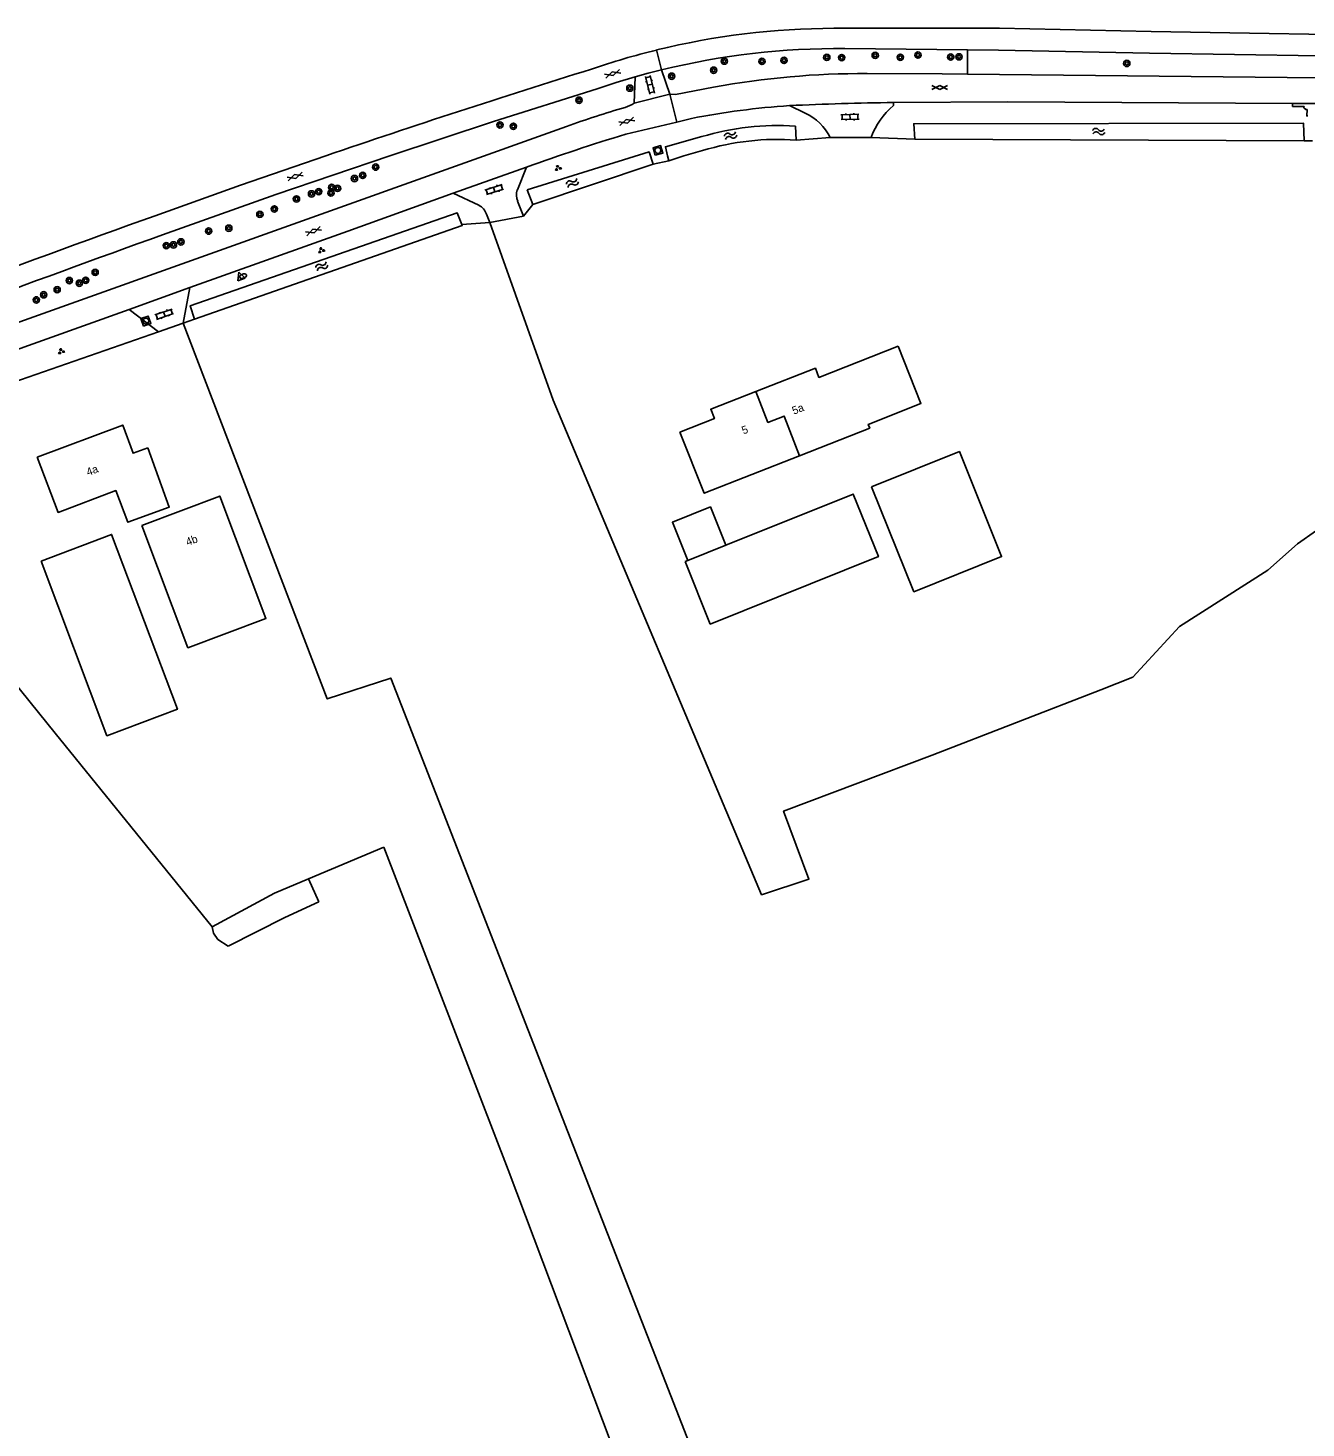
# Model space of a CAD drawing. Extents: x 134297 to 137000, y 403500 to 406000.
# Drawn here: x 136615.3 to 136777.7, y 405338.4 to 405516.2 of the extents above; entities that cross this region are included whole.
import ezdxf

# ---------------------------------------------------------------- set-up
doc = ezdxf.new("R2010")
doc.units = 0
for name, color, linetype in [('gg-afsc-draadraster', 7, 'Continuous'), ('gg-afsc-erfafscheiding', 7, 'Continuous'), ('gg-anno-huisnummerreeks BGT', 7, 'Continuous'), ('gg-bbg-bijgebouw', 7, 'Continuous'), ('gg-bbg-gedigitaliseerde bebouwing', 7, 'Continuous'), ('gg-bbg-gedigitaliseerde bijgebouw', 7, 'Continuous'), ('gg-bbg-hoofdgebouw', 7, 'Continuous'), ('gg-bbg-luifel en loopbrug', 7, 'Continuous'), ('gg-bbg-tussenscheiding', 7, 'Continuous'), ('gg-knt-bronhoudergrens', 7, 'Continuous'), ('gg-knt-verharding', 7, 'Continuous'), ('gg-kntw-bovenkant insteek waterloop', 7, 'Continuous'), ('gt-grn-groengrens', 7, 'Continuous'), ('gt-grn-weggrens', 7, 'Continuous'), ('gt-symb-boom', 7, 'Continuous'), ('gt-symb-brandkraan', 7, 'Continuous'), ('gt-symb-gesloten verharding', 7, 'Continuous'), ('gt-symb-groenvak', 7, 'Continuous'), ('gt-symb-klinker verharding', 7, 'Continuous'), ('gt-symb-rioolschacht', 7, 'Continuous'), ('gt-symb-waterafsluiter', 7, 'Continuous'), ('gt-symb-watersymbool', 7, 'Continuous')]:
    doc.layers.add(name, color=color, linetype=linetype)

# ---------------------------------------------------------------- blocks, each defined once
blk = doc.blocks.new('gt0-BOOM')
at = {"layer": 'gt-symb-boom'}
for radius in [0.4, 0.2]:
    blk.add_circle((0, 0), radius, dxfattribs=at)
blk = doc.blocks.new('gt0-GESVH1')
at = {"layer": 'gt-symb-gesloten verharding'}
for p, q in [((-0.99, -0.26), (0.01, 0.24)), ((0.01, -0.26), (-0.99, 0.24)), ((0.01, 0.24), (1.01, -0.26)), ((1.01, 0.24), (0.01, -0.26))]:
    blk.add_line(p, q, dxfattribs=at)
blk = doc.blocks.new('gt0-WA')
at = {"layer": 'gt-symb-watersymbool'}
for centre, start, end in [((-0.32, 0.02), 28.0725, 151.9275), ((0.43, 0.42), 208.0725, 331.9275), ((-0.32, -0.43), 28.0725, 151.9275), ((0.43, -0.03), 208.0725, 331.9275)]:
    blk.add_arc(centre, 0.425, start, end, dxfattribs=at)
blk = doc.blocks.new('gt0-KL1')
at = {"layer": 'gt-symb-klinker verharding'}
for p, q in [((-1.15, 0.3), (1.15, 0.3)), ((-1, -0.3), (-1, 0.3)), ((-0.5, 0.3), (-0.5, 0.45)), ((0, -0.3), (0, 0.3)), ((0.5, 0.3), (0.5, 0.45)), ((1, -0.3), (1, 0.3)), ((-1.15, -0.3), (1.15, -0.3)), ((-0.5, -0.45), (-0.5, -0.3)), ((0.5, -0.45), (0.5, -0.3))]:
    blk.add_line(p, q, dxfattribs=at)
blk = doc.blocks.new('gt0-RS')
at = {"layer": 'gt-symb-rioolschacht'}
blk.add_lwpolyline([(-0.5, -0.5), (0.5, -0.5), (0.5, 0.5), (-0.5, 0.5)], close=True, dxfattribs=at)
blk.add_circle((0, 0), 0.375, dxfattribs=at)
blk = doc.blocks.new('gt0-GRVAK')
at = {"layer": 'gt-symb-groenvak'}
for p, q in [((-0.11, 0.19), (-0.23, 0.24)), ((-0.18, 0.15), (0.09, 0.15)), ((-0.09, 0.21), (-0.16, 0.32)), ((-0.05, 0.21), (-0.05, 0.39)), ((0, 0.21), (0.06, 0.32)), ((0.01, 0.19), (0.13, 0.24)), ((0.26, -0.05), (0.2, 0.06)), ((0.3, -0.05), (0.3, 0.13)), ((0.35, -0.05), (0.41, 0.06)), ((-0.24, -0.23), (-0.36, -0.18)), ((-0.32, -0.26), (-0.05, -0.26)), ((-0.23, -0.21), (-0.29, -0.09)), ((-0.18, -0.2), (-0.18, -0.02)), ((-0.14, -0.21), (-0.07, -0.09)), ((-0.12, -0.23), (0, -0.18)), ((0.24, -0.07), (0.12, -0.02)), ((0.17, -0.11), (0.44, -0.11)), ((0.37, -0.07), (0.49, -0.02))]:
    blk.add_line(p, q, dxfattribs=at)
blk = doc.blocks.new('gt0-WAFSL')
at = {"layer": 'gt-symb-waterafsluiter'}
for p, q in [((-0.5, -0.33), (0, 0.67)), ((0, 0.67), (0.5, -0.33)), ((0.5, -0.33), (-0.5, -0.33))]:
    blk.add_line(p, q, dxfattribs=at)
blk = doc.blocks.new('gt0-BR')
at = {"layer": 'gt-symb-brandkraan'}
for centre, radius, start, end in [((-0.24, 0), 0.206, 107.5669, 252.4331), ((0.6, -2.66), 3, 106.892, 107.5669), ((0, -0.69), 0.938, 73.108, 106.892), ((-0.6, -2.66), 3, 72.4331, 73.108), ((0.24, 0), 0.206, 287.567, 72.4331), ((0.6, 2.66), 3, 252.4331, 253.108), ((0, 0.69), 0.938, 253.108, 286.8921), ((-0.6, 2.66), 3, 286.8921, 287.567)]:
    blk.add_arc(centre, radius, start, end, dxfattribs=at)

msp = doc.modelspace()

# ---------------------------------------------------------------- linework, layer by layer
at = {"layer": 'gg-afsc-draadraster'}
msp.add_line((136650.97, 405408.14), (136660.53, 405412.14), dxfattribs=at)
for points in [[(136589.32, 405463.15), (136618.79, 405426.65), (136638.74, 405402.04)], [(136638.74, 405402.04), (136646.65, 405406.33), (136650.97, 405408.14)]]:
    msp.add_lwpolyline(points, dxfattribs=at)
at = {"layer": 'gg-afsc-erfafscheiding'}
for p, q in [((136636.51, 405479.23), (136635.07, 405478.73)), ((136631.91, 405477.62), (136612.46, 405470.83)), ((136635.07, 405478.73), (136631.91, 405477.62))]:
    msp.add_line(p, q, dxfattribs=at)
at = {"layer": 'gg-bbg-bijgebouw'}
for p, q in [((136703.99, 405450.51), (136699.17, 405448.57)), ((136699.17, 405448.57), (136698.82, 405448.43))]:
    msp.add_line(p, q, dxfattribs=at)
for points in [[(136722.52, 405457.94), (136733.67, 405462.42), (136739.03, 405449.08), (136727.88, 405444.6), (136722.52, 405457.94)], [(136698.82, 405448.43), (136702.01, 405440.49), (136723.37, 405449.06), (136720.18, 405457.01), (136703.99, 405450.51)]]:
    msp.add_lwpolyline(points, dxfattribs=at)
at = {"layer": 'gg-bbg-gedigitaliseerde bebouwing'}
for points in [[(136630.57, 405462.88), (136633.3, 405455.36), (136628.02, 405453.44), (136626.52, 405457.45), (136619.16, 405454.69), (136616.53, 405461.68)], [(136629.81, 405453.03), (136639.71, 405456.76), (136645.57, 405441.21), (136635.67, 405437.48), (136629.81, 405453.03)]]:
    msp.add_lwpolyline(points, dxfattribs=at)
at = {"layer": 'gg-bbg-gedigitaliseerde bijgebouw'}
msp.add_lwpolyline([(136617, 405448.5), (136625.96, 405451.88), (136634.33, 405429.67), (136625.37, 405426.3), (136617, 405448.5)], dxfattribs=at)
at = {"layer": 'gg-bbg-hoofdgebouw'}
for points in [[(136725.88, 405475.8), (136715.83, 405471.84), (136715.37, 405472.99), (136707.82, 405470.04)], [(136725.88, 405475.8), (136728.77, 405468.53), (136722.08, 405465.87), (136722.27, 405465.4), (136713.35, 405461.89)], [(136707.82, 405470.04), (136702.09, 405467.79), (136702.55, 405466.6), (136698.15, 405464.89)], [(136616.53, 405461.68), (136627.38, 405465.77), (136628.69, 405462.19), (136630.57, 405462.88)], [(136698.15, 405464.89), (136701.26, 405457.12), (136713.35, 405461.89)]]:
    msp.add_lwpolyline(points, dxfattribs=at)
at = {"layer": 'gg-bbg-luifel en loopbrug'}
msp.add_lwpolyline([(136699.17, 405448.57), (136697.22, 405453.43), (136702.04, 405455.37), (136703.99, 405450.51)], dxfattribs=at)
at = {"layer": 'gg-bbg-tussenscheiding'}
msp.add_lwpolyline([(136707.82, 405470.04), (136709.35, 405466.11), (136711.4, 405466.91), (136713.35, 405461.89)], dxfattribs=at)
at = {"layer": 'gg-knt-bronhoudergrens'}
for points in [[(136674.02, 405491.52), (136682.07, 405468.96), (136708.54, 405406.12), (136714.55, 405408.09), (136711.33, 405416.73), (136730.21, 405423.84)], [(136747.27, 405272.72), (136735.91, 405297.9), (136732.87, 405304.52), (136727.31, 405306.5), (136719.9, 405306.37), (136711.43, 405305.44), (136661.43, 405433.63), (136653.36, 405430.99), (136635.07, 405478.73)], [(136730.21, 405423.84), (136751.64, 405432.16), (136755.68, 405433.76), (136761.61, 405440.18), (136772.84, 405447.35), (136776.6, 405450.71), (136781.44, 405454.06), (136784.85, 405455.99), (136795.36, 405461.05)], [(136742.28, 405189.36), (136742.92, 405191.5), (136743.21, 405194.1), (136743.65, 405198.46), (136744.04, 405202.64), (136743.79, 405206.82), (136741.21, 405216.26), (136726.34, 405261.39), (136725.2, 405266.08), (136726.77, 405269.13), (136728.63, 405270.7), (136732.18, 405273.77), (136725.75, 405296.24), (136722.54, 405300.13), (136719.75, 405301.96), (136716.32, 405302.28), (136702.49, 405300.68), (136701.82, 405302.46), (136696.04, 405318.89), (136676.33, 405371.15), (136660.53, 405412.14)]]:
    msp.add_lwpolyline(points, dxfattribs=at)
at = {"layer": 'gg-knt-verharding'}
for p, q in [((136719.12, 405513.61), (136734.69, 405513.46)), ((136692.34, 405506.69), (136692.49, 405510.03)), ((136696.88, 405507.81), (136695.81, 405510.91)), ((136734.68, 405510.35), (136779.37, 405509.87)), ((136692.34, 405506.69), (136696.88, 405507.81)), ((136714.07, 405505.41), (136712.09, 405506.37)), ((136725.31, 405506.77), (136725.28, 405506.37)), ((136776, 405506.64), (136785.63, 405506.59)), ((136697.75, 405504.28), (136691.29, 405502.74)), ((136699.64, 405504.73), (136697.75, 405504.28)), ((136722.44, 405502.33), (136717.26, 405502.3)), ((136678.67, 405498.56), (136669.36, 405495.24)), ((136678.67, 405498.56), (136677.51, 405495.67)), ((136672.62, 405493.7), (136669.36, 405495.24)), ((136677.55, 405494.21), (136678.3, 405492.33)), ((136674.02, 405491.52), (136673.59, 405492.57)), ((136635.89, 405483.24), (136628.2, 405480.47)), ((136635.89, 405483.24), (136635.07, 405478.73)), ((136628.2, 405480.47), (136611.98, 405474.65)), ((136628.2, 405480.47), (136631.91, 405477.62))]:
    msp.add_line(p, q, dxfattribs=at)
for points in [[(136793.04, 405515.18), (136758.04, 405515.79), (136738.77, 405516.22), (136717.73, 405516.18)], [(136734.69, 405513.46), (136738.63, 405513.42), (136757.83, 405513.01), (136779.4, 405512.67)], [(136632.43, 405489.93), (136646.84, 405495.05), (136661.32, 405500), (136674.47, 405504.33), (136687.66, 405508.51), (136690.06, 405509.3), (136692.49, 405510.03)], [(136692.49, 405510.03), (136694.15, 405510.48), (136695.81, 405510.91)], [(136721.94, 405510.43), (136731.47, 405510.38), (136734.68, 405510.35)], [(136696.88, 405507.81), (136697.6, 405507.79), (136702.44, 405508.7)], [(136776, 405506.64), (136739.8, 405506.84), (136725.31, 405506.77)], [(136777.92, 405505.06), (136777.8, 405505.06), (136777.83, 405505.86), (136777.66, 405505.86), (136777.43, 405506.09), (136777.46, 405506.24), (136776, 405506.27), (136776, 405506.64)], [(136582.58, 405467.6), (136620.83, 405481.22), (136683.74, 405503.72)], [(136631.5, 405492.38), (136642.33, 405496.24), (136653.2, 405500)], [(136669.36, 405495.24), (136655.97, 405490.41), (136635.89, 405483.24)]]:
    msp.add_lwpolyline(points, dxfattribs=at)
for centre, radius, start, end in [((136717.93, 405420.84), 95.34, 90.1183, 103.7956), ((136717.95, 405420.78), 95.4, 103.8009, 108.9699), ((136718.24, 405419.31), 94.3, 89.463, 103.7572), ((137070.3, 404277.92), 1291.3, 107.27032, 108.84495), ((136721.35, 405406.37), 104.06, 89.6736, 100.4705), ((136723.75, 405393.15), 117.58, 106.0577, 109.8907), ((136690.32, 405509.39), 3.37, 285.5386, 306.8092), ((136718.68, 405408.38), 98.21, 93.8486, 101.1791), ((136732.38, 405055.26), 451.56, 90.8973, 92.5762), ((136731.59, 405498.9), 9.77, 130.2212, 159.4541), ((136711.19, 405499.25), 6.79, 26.6405, 64.9242), ((136767.66, 405251.17), 262.9, 106.8873, 109.7835), ((136679.37, 405494.99), 1.98, 160.1046, 203.4287), ((136671.67, 405491.9), 2.04, 19.1831, 62.0362), ((137029.97, 404371.11), 1189.96, 109.56404, 112.34001), ((137025.75, 404381.73), 1175.93, 109.54087, 112.19315)]:
    msp.add_arc(centre, radius, start, end, dxfattribs=at)
at = {"layer": 'gg-kntw-bovenkant insteek waterloop'}
for p, q in [((136712.84, 405503.75), (136712.93, 405501.99)), ((136701.04, 405500.66), (136698.67, 405500)), ((136727.99, 405502.09), (136777.48, 405501.88)), ((136679.46, 405493.82), (136694.76, 405498.92)), ((136696.59, 405500), (136696.74, 405499.34)), ((136696.74, 405499.34), (136698.67, 405500)), ((136678.75, 405495.66), (136679.46, 405493.82)), ((136650.97, 405408.14), (136652.31, 405405.21))]:
    msp.add_line(p, q, dxfattribs=at)
for points in [[(136777.48, 405501.88), (136777.39, 405504.12), (136727.86, 405504.06), (136727.99, 405502.09)], [(136696.59, 405500), (136696.33, 405501.14), (136700.95, 405502.42)], [(136678.75, 405495.66), (136694.24, 405500.49), (136694.76, 405498.92)], [(136670.46, 405491.25), (136669.87, 405492.72), (136635.96, 405480.93), (136636.51, 405479.23)], [(136636.51, 405479.23), (136670.51, 405491.12), (136670.46, 405491.25)], [(136652.31, 405405.21), (136647.97, 405403.22), (136640.79, 405399.59)], [(136640.79, 405399.59), (136639.46, 405400.43), (136638.91, 405401.21), (136638.74, 405402.04)]]:
    msp.add_lwpolyline(points, dxfattribs=at)
for centre in [(136710.55, 405470.43), (136710.65, 405468.67)]:
    msp.add_arc(centre, 33.4, 86.0799, 106.721, dxfattribs=at)
at = {"layer": 'gt-grn-groengrens'}
for p, q in [((136734.69, 405513.46), (136734.68, 405510.35)), ((136717.26, 405502.3), (136712.93, 405501.99)), ((136727.99, 405502.09), (136722.44, 405502.33)), ((136778.54, 405501.88), (136777.48, 405501.88)), ((136694.76, 405498.92), (136696.74, 405499.34)), ((136678.3, 405492.33), (136679.46, 405493.82)), ((136670.46, 405491.25), (136674.02, 405491.52))]:
    msp.add_line(p, q, dxfattribs=at)
at = {"layer": 'gt-grn-weggrens'}
for p, q in [((136695.81, 405510.91), (136695.19, 405513.43)), ((136696.88, 405507.81), (136697.75, 405504.28)), ((136674.02, 405491.52), (136678.3, 405492.33))]:
    msp.add_line(p, q, dxfattribs=at)

# ---------------------------------------------------------------- block references
at = {"layer": 'gt-symb-boom'}
for p in [(136716.82, 405512.49), (136718.72, 405512.46), (136722.97, 405512.74), (136726.16, 405512.5), (136728.4, 405512.78), (136732.57, 405512.53), (136733.62, 405512.56), (136702.45, 405510.86), (136703.8, 405512.01), (136708.58, 405511.98), (136711.39, 405512.11), (136754.93, 405511.72), (136697.12, 405510.1), (136691.8, 405508.58), (136685.35, 405507.05), (136675.3, 405503.91), (136677.01, 405503.74), (136659.52, 405498.55), (136656.82, 405497.1), (136657.87, 405497.5), (136651.36, 405495.15), (136652.28, 405495.43), (136653.83, 405495.26), (136653.92, 405495.97), (136654.67, 405495.85), (136646.65, 405493.24), (136649.45, 405494.51), (136644.8, 405492.55), (136638.29, 405490.42), (136640.86, 405490.79), (136632.91, 405488.57), (136633.83, 405488.67), (136634.77, 405489.05), (136620.61, 405484.14), (136622.68, 405484.17), (136623.88, 405485.17), (136617.34, 405482.33), (136619.05, 405482.97), (136621.86, 405483.8), (136616.41, 405481.68)]:
    msp.add_blockref('gt0-BOOM', p, dxfattribs=at)
at = {"layer": 'gt-symb-brandkraan', "rotation": 19.684642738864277}
msp.add_blockref('gt0-BR', (136642.68, 405484.7), dxfattribs=at)
at = {"layer": 'gt-symb-gesloten verharding'}
for p, rotation in [((136689.6, 405510.42), 18.000074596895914), ((136691.4, 405504.37), 18.000074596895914), ((136649.27, 405497.36), 18.000074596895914), ((136651.6, 405490.42), 19.992893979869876)]:
    msp.add_blockref('gt0-GESVH1', p, dxfattribs=dict(at, rotation=rotation))
msp.add_blockref('gt0-GESVH1', (136731.16, 405508.67), dxfattribs=at)
at = {"layer": 'gt-symb-groenvak'}
for p in [(136682.66, 405498.42), (136652.59, 405487.98), (136619.55, 405475.14)]:
    msp.add_blockref('gt0-GRVAK', p, dxfattribs=at)
at = {"layer": 'gt-symb-klinker verharding'}
for p, rotation in [((136694.36, 405509.01), -76.46414363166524), ((136719.77, 405504.92), 2.006538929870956), ((136674.58, 405495.7), 17.58309712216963), ((136632.66, 405479.86), 19.033079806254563)]:
    msp.add_blockref('gt0-KL1', p, dxfattribs=dict(at, rotation=rotation))
at = {"layer": 'gt-symb-rioolschacht'}
for p, rotation in [((136695.37, 405500.67), 16.98473253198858), ((136630.32, 405478.99), 19.03307980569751)]:
    msp.add_blockref('gt0-RS', p, dxfattribs=dict(at, rotation=rotation))
at = {"layer": 'gt-symb-waterafsluiter', "rotation": 19.684642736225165}
msp.add_blockref('gt0-WAFSL', (136642.35, 405484.59), dxfattribs=at)
at = {"layer": 'gt-symb-watersymbool'}
for p, rotation in [((136704.54, 405502.53), 20.971710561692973), ((136751.3, 405503.07), 7.004259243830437), ((136684.45, 405496.51), 28.998977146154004), ((136652.61, 405485.92), 28.998977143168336)]:
    msp.add_blockref('gt0-WA', p, dxfattribs=dict(at, rotation=rotation))

# ---------------------------------------------------------------- texts
at = {"layer": 'gg-anno-huisnummerreeks BGT'}
for s, rotation, p in [('5a', 21.4, (136712.64, 405467.09)), ('5', 21.4, (136706.24, 405464.58)), ('4a', 20.7, (136622.98, 405459.3)), ('4b', 20.7, (136635.62, 405450.41))]:
    msp.add_text(s, height=1, rotation=rotation, dxfattribs=at).set_placement(p)

doc.saveas('drawing.dxf')
